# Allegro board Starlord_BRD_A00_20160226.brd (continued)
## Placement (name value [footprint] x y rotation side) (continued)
R2030  10KR2J-3-GP  [R402H16]  109.5 31.13 180 bottom
R2039  10KR2J-3-GP  [R402H16]  113.21 24.68 90 bottom
R2040  10KR2J-3-GP  [R402H16]  114.35 27.91 0 bottom
R2041  10KR2J-3-GP  [R402H16]  109.4 19.96 0 bottom
R2042  10KR2J-3-GP  [R402H16]  111.99 19.8 0 bottom
R2043  10KR2J-3-GP  [R402H16]  108.56 19.96 0 bottom
R2044  10KR2J-3-GP  [R402H16]  112.88 30.88 0 bottom
R2045  10KR2J-3-GP  [R402H16]  136.57 18.38 0 top
R2046  10KR2J-3-GP  [R402H16]  114.6 31.59 0 bottom
R2047  10KR2J-3-GP  [R402H16]  115.49 31.59 0 bottom
R2048  51KR2J-1-GP  [R402H16]  111.17 31.13 0 bottom
R2049  51KR2J-1-GP  [R402H16]  112.04 30.88 0 bottom
R2101  -  [0R0402-PAD]  55.17 9.49 180 bottom
R2102  0R2J-2-GP  [R402H16]  56.01 9.44 180 bottom
R2106  -  [0R0603-PAD]  72.03 5.07 0 top
R2107  -  [0R0603-PAD]  120.11 38.55 90 top
R2108  -  [0R0603-PAD]  114.7 42.36 90 top
R2109  -  [0R0603-PAD]  137.72 42.26 90 bottom
R2110  -  [0R0603-PAD]  137.72 43.53 90 bottom
R2111  -  [0R0603-PAD]  135.48 39.64 90 bottom
R2402  -  [0R0402-PAD]  179.02 30.75 90 top
R2403  -  [0R0402-PAD]  185.32 29.79 270 bottom
R2405  10R2F-L-GP  [R402H14]  198.55 42.38 270 bottom
R2407  -  [0R0402-PAD]  187.96 28.74 180 bottom
R2414  4K7R2J-2-GP  [R402H16]  134.75 5.76 270 top
R2415  10KR2J-3-GP  [R402H16]  186.21 27.7 0 bottom
R2417  100KR2J-1-GP  [R402H16]  190.55 41.39 270 bottom
R2418  0R2J-2-GP  [R402H16]  189.28 41.34 180 bottom
R2419  -  [0R0402-PAD]  198.65 41.47 90 bottom
R2421  330R2J-3-GP  [R402H16]  190.22 31.08 180 bottom
R2422  330R2J-3-GP  [R402H16]  185.07 31.08 180 bottom
R2423  330R2J-3-GP  [R402H16]  189.23 29.15 90 bottom
R2424  20KR2F-L-GP  [R402H16]  195.68 44.11 180 bottom
R2429  10KR2J-3-GP  [R402H16]  189.25 38.04 180 bottom
R2430  10KR2J-3-GP  [R402H16]  187.2 41.49 90 bottom
R2432  1KR2J-1-GP  [R402H16]  191.03 30.95 0 bottom
R2434  100KR2J-1-GP  [R402H16]  198.78 34.61 90 bottom
R2435  -  [0R0402-PAD]  185.08 34.43 0 bottom
R2436  100KR2J-1-GP  [R402H16]  184.96 32.76 180 bottom
R2437  43R2J-GP  [R402H16]  178.87 33.54 270 top
R2441  100KR2F-L1-GP  [R402H16]  187.78 31.11 0 bottom
R2442  64K9R2F-1-GP  [R402H16]  186.32 30.6 270 bottom
R2443  33KR2F-GP  [R402H16]  191.82 32.22 90 bottom
R2444  100KR2F-L1-GP  [R402H16]  190.57 32.81 0 bottom
R2445  -  [0R0402-PAD]  190.52 28.72 180 bottom
R2446  -  [0R0603-PAD]  201.67 33.65 270 top
R2447  0R2J-2-GP  [R402H16]  199.13 35.96 0 bottom
R2448  10KR2F-2-GP  [R402H16]  196.49 44.11 0 bottom
R2449  100KR2J-1-GP  [R402H16]  185.7 43.76 180 bottom
R2450  100KR2J-1-GP  [R402H16]  185.5 42.38 90 bottom
R2451  100KR2J-1-GP  [R402H16]  192.68 30.95 180 bottom
R2454  100KR2J-1-GP  [R402H16]  181.84 25.54 0 top
R2459  0R2J-2-GP  [R402H16]  198.3 35.96 0 bottom
R2462  -  [0R0402-PAD]  187.81 43.53 90 bottom
R2463  1KR2J-1-GP  [R402H16]  182.7 25.54 180 top
R2470  -  [0R0402-PAD]  198.35 39.84 270 bottom
R2471  0R2J-2-GP  [R402H16]  198.35 40.66 270 bottom
R2472  -  [0R0402-PAD]  193.67 36.72 90 bottom
R2473  10KR2J-3-GP  [R402H16]  191.79 28.31 270 bottom
R2474  0R2J-2-GP  [R402H16]  179.63 52.67 0 top
R2475  -  [0R0402-PAD]  178.74 52.67 0 top
R2480  100KR2J-1-GP  [R402H16]  134.72 6.62 270 top
R2489  100KR2J-1-GP  [R402H16]  186.31 32.73 270 bottom
R2494  0R2J-2-GP  [R402H16]  188.01 32.83 270 bottom
R2495  100KR2J-1-GP  [R402H16]  186.51 43.63 0 bottom
R2496  100KR2J-1-GP  [R402H16]  193.67 35.02 270 bottom
R2497  0R2J-2-GP  [R402H16]  185.34 28.97 270 bottom
R2501  4K7R2J-2-GP  [R402H16]  84.45 12.67 0 bottom
R2503  10R2F-L-GP  [R402H14]  74.09 7.33 90 bottom
R2504  10MR2J-L-GP  [R402H16]  71.88 7.43 90 bottom
R2510  10KR2F-2-GP  [R402H16]  184.88 43.76 0 bottom
R2515  -  [0R0402-PAD]  80.72 12.67 180 bottom
R2601  0R2J-2-GP  [R402H16]  139.98 22.29 270 bottom
R2602  -  [0R0402-PAD]  144.58 20.72 270 bottom
R2603  7K5R2F-1-GP  [R402H16]  133.83 24.2 180 bottom
R2604  7K5R2F-1-GP  [R402H16]  139.98 23.13 90 bottom
R2607  10KR2J-3-GP  [R402H16]  144.58 19.9 270 bottom
R2608  27KR2F-L-GP  [R402H16]  122.12 29.46 90 bottom
R2609  10R2F-L-GP  [R402H14]  122.12 28.64 90 bottom
R2610  NTC-100K-8-GP  [NTC-603H38]  122.86 31.72 180 bottom
R2611  -  [0R0402-PAD]  194.21 41.57 90 bottom
R2612  -  [0R0402-PAD]  149.02 77.94 90 top
R2613  -  [0R0402-PAD]  149.02 77.05 90 top
R2614  -  [0R0402-PAD]  149.02 76.17 90 top
R2615  0R2J-2-GP  [R402H16]  144.58 21.53 270 bottom
R2702  -  [0R0805-PAD]  28.4 16.32 180 bottom
R2703  -  [0R0603-PAD]  24.08 11.68 180 bottom
R2704  -  [0R0805-PAD]  30.1 16.32 180 bottom
R2705  0R2J-2-GP  [R402H16]  24.79 23.46 270 top
R2706  -  [0R0805-PAD]  20.32 10.46 180 bottom
R2708  -  [0R0402-PAD]  29.26 13.81 270 top
R2709  200KR2F-L-GP  [R402H16]  27.99 11.01 90 top
R2710  0R2J-2-GP  [R402H16]  24.79 22.65 270 top
R2711  100KR2J-1-GP  [R402H16]  19 12.08 0 bottom
R2713  -  [0R0402-PAD]  24.79 21.84 270 top
R2714  -  [0R0402-PAD]  29.28 14.62 270 top
R2716  -  [0R0402-PAD]  29.28 16.4 270 top
R2717  2K2R2J-2-GP  [R402H16]  25.88 13.07 0 bottom
R2718  -  [0R0402-PAD]  32.76 19.24 270 top
R2719  -  [0R0402-PAD]  29.28 19.96 270 top
R2720  -  [0R0402-PAD]  29.28 18.18 270 top
R2722  100KR2J-1-GP  [R402H16]  27.99 11.9 270 top
R2723  -  [0R0402-PAD]  20.01 15.41 0 bottom
R2724  -  [0R0402-PAD]  24.48 19.96 0 bottom
R2725  -  [0R0402-PAD]  26.72 11.47 180 top
R2726  10KR2J-3-GP  [R402H16]  19.3 28.85 0 bottom
R2727  20KR2J-L2-GP  [R402H16]  18.46 28.85 180 bottom
R2728  100KR2J-1-GP  [R402H16]  30.28 12.41 0 top
R2731  -  [0R0805-PAD]  29.97 22.37 0 top
R2732  0R2J-2-GP  [R402H16]  29.28 17.29 90 top
R2905  -  [0R0402-PAD]  18.03 24.53 270 bottom
R2906  -  [0R0603-PAD]  16.31 14.7 180 top
R2907  -  [0R0603-PAD]  17.02 19.93 90 top
R2908  10R2F-L-GP  [R402H14]  16.97 17.21 90 bottom
R2909  -  [0R0603-PAD]  20.24 22.75 90 top
R2910  10R2F-L-GP  [R402H14]  16.97 21.56 90 bottom
R2911  -  [0R0603-PAD]  17.58 14.7 180 top
R2912  2K2R2J-2-GP  [R402H16]  16.97 18.1 270 bottom
R2913  2K2R2J-2-GP  [R402H16]  16.97 23.44 90 bottom
R2919  10KR2J-3-GP  [R402H16]  16.97 18.99 270 bottom
R2920  10KR2J-3-GP  [R402H16]  16.97 19.85 270 bottom
R2921  -  [0R0402-PAD]  16.97 22.62 90 bottom
R2922  -  [0R0402-PAD]  16.97 16.32 270 bottom
R2923  -  [0R0603-PAD]  17.04 21.23 90 top
R3401  -  [0R0402-PAD]  20.01 45 0 bottom
R3402  -  [0R0402-PAD]  18.39 45.51 0 bottom
R3403  20KR2F-L-GP  [R402H16]  24.1 43.91 270 bottom
R3404  22K1R2F-L-GP  [R402H16]  24.1 44.72 270 bottom
R3405  -  [0R0402-PAD]  20.83 45 0 bottom
R3406  -  [0R0402-PAD]  19.2 45.51 0 bottom
R3501  100KR2J-1-GP  [R402H16]  20.75 39.44 270 bottom
R3605  -  [0R0402-PAD]  22.02 54.04 270 top
R3606  -  [0R0402-PAD]  22.02 54.86 270 top
R3609  -  [0R0402-PAD]  22.02 51.88 270 top
R3610  -  [0R0402-PAD]  22.02 52.7 270 top
R3611  -  [0R0402-PAD]  22.15 31.69 270 top
R3612  -  [0R0402-PAD]  22.15 29.53 270 top
R3613  -  [0R0402-PAD]  22.15 30.34 270 top
R3614  -  [0R0402-PAD]  22.15 32.5 270 top
R3701  -  [0R0402-PAD]  26.87 41.11 0 top
R3702  -  [0R0402-PAD]  28.17 41.55 90 top
R3703  100KR2J-1-GP  [R402H16]  36.75 37.18 180 top
R3704  10KR2F-2-GP  [R402H16]  35.86 37.18 180 top
R3705  -  [0R0402-PAD]  30.28 37.18 0 top
R3706  -  [0R0402-PAD]  38.4 41.37 270 top
R3707  2K2R2J-2-GP  [R402H16]  31.16 37.18 180 top
R3708  4K7R2J-2-GP  [R402H16]  32.05 37.18 180 top
R3709  -  [0R0402-PAD]  31.37 48.35 0 top
R3710  -  [0R0402-PAD]  24.23 43.76 270 top
R3711  200KR2J-L2-GP  [R402H16]  38.4 40.38 90 top
R3712  200KR2J-L2-GP  [R402H16]  38.4 42.26 90 top
R3713  909KR2F-GP  [R402H16]  29.03 49.01 270 top
R3714  909KR2F-GP  [R402H16]  30.38 49.57 180 top
R3715  909KR2F-GP  [R402H16]  20.75 95.95 270 top
R3716  301KR2F-1-GP  [R402H16]  20.65 96.79 270 top
R3717  10KR2F-2-GP  [R402H16]  40.69 41.37 270 top
R3718  -  [0R0402-PAD]  38.4 44.03 270 top
R3719  0R2J-2-GP  [R402H16]  38.4 43.15 270 top
R3720  0R2J-2-GP  [R402H16]  32.18 46.57 180 top
R3721  0R2J-2-GP  [R402H16]  33.07 46.57 180 top
R3722  10KR2F-2-GP  [R402H16]  27.1 46.83 90 top
R3723  10KR2F-2-GP  [R402H16]  23.65 48.66 180 top
R3801  100KR2J-1-GP  [R402H16]  33.04 63.97 90 top
R3802  100KR2J-1-GP  [R402H16]  34.82 63.97 270 top
R3803  4K99R2F-L-GP  [R402H16]  27.76 53.43 0 top
R3810  4K7R2J-2-GP  [R402H16]  29.01 61.31 270 top
R3811  4K7R2J-2-GP  [R402H16]  38.4 60.42 90 top
R3812  10KR2J-3-GP  [R402H16]  37.39 64.13 180 top
R3813  10KR2J-3-GP  [R402H16]  39.75 64.35 270 top
R3814  10KR2J-3-GP  [R402H16]  38.91 62.86 270 top
R3815  4K7R2J-2-GP  [R402H16]  38.5 58.18 270 top
R3816  4K7R2J-2-GP  [R402H16]  38.5 59 270 top
R3817  4K7R2J-2-GP  [R402H16]  29.01 56.23 90 top
R3818  4K7R2J-2-GP  [R402H16]  29.01 57.09 90 top
R3819  4K7R2J-2-GP  [R402H16]  29.01 58.79 90 top
R3820  4K7R2J-2-GP  [R402H16]  29.01 57.95 90 top
R3821  4K7R2J-2-GP  [R402H16]  38.2 56.18 270 top
R3822  4K7R2J-2-GP  [R402H16]  38.2 55.34 270 top
R3823  4K7R2J-2-GP  [R402H16]  28.6 53.43 180 top
R3824  4K7R2J-2-GP  [R402H16]  29.44 53.43 180 top
R3830  2MR2F-GP  [R402H16]  15.44 96.41 180 top
R3831  2MR2F-GP  [R402H16]  15.44 94.73 0 top
R3832  -  [0R0402-PAD]  18.67 91.79 270 top
R3833  -  [0R0402-PAD]  18.67 92.6 270 top
R3834  -  [0R0402-PAD]  21.77 92.8 270 top
R3835  -  [0R0402-PAD]  21.77 93.62 270 top
R3836  -  [0R0402-PAD]  17.47 97.53 270 top
R3837  -  [0R0402-PAD]  17.47 96.71 270 top
R3838  -  [0R0402-PAD]  16.56 99.69 270 top
R3839  -  [0R0402-PAD]  16.56 98.87 270 top
R3842  0R2J-2-GP  [R402H16]  29.01 60.47 270 top
R3843  -  [0R0402-PAD]  36.57 64.13 180 top
R3844  0R2J-2-GP  [R402H16]  41.07 63.52 90 top
R3845  0R2J-2-GP  [R402H16]  41.07 62.7 90 top
R3846  -  [0R0402-PAD]  29.01 59.63 270 top
R3847  0R2J-2-GP  [R402H16]  24.48 61.03 90 top
R3848  0R2J-2-GP  [R402H16]  24.48 61.87 90 top
R3849  -  [0R0402-PAD]  26.21 61.87 90 top
R3850  -  [0R0402-PAD]  26.21 61.03 90 top
R4002  -  [0R0402-PAD]  162.02 100.35 270 bottom
R4005  1KR2J-1-GP  [R402H16]  162.02 101.16 90 bottom
R4006  20KR2F-L-GP  [R402H16]  117.47 18 0 bottom
R4009  10KR2J-3-GP  [R402H16]  116.66 18 0 bottom
R4010  -  [0R0402-PAD]  130.35 101.95 270 bottom
R4011  -  [0R0402-PAD]  161.34 102.86 180 bottom
R4017  -  [0R0402-PAD]  86.82 90.19 0 top
R4018  0R2J-2-GP  [R402H16]  95.86 92.85 90 top
R4019  0R2J-2-GP  [R402H16]  100 92.55 270 bottom
R4021  -  [0R1206-PAD]  106.12 95.19 90 top
R4022  -  [0R1206-PAD]  106.12 93.08 270 top
R4023  -  [0R0402-PAD]  104.54 11.35 180 bottom
R4024  -  [0R0402-PAD]  106.2 16.55 0 bottom
R4026  10KR2J-3-GP  [R402H16]  99.06 10.71 180 bottom
R4027  10KR2J-3-GP  [R402H16]  109.02 96.87 90 bottom
R4028  10KR2J-3-GP  [R402H16]  109.02 95.98 90 bottom
R4029  -  [0R0402-PAD]  158.72 104.69 180 bottom
R4030  -  [0R0402-PAD]  159.61 104.69 180 bottom
R4031  100KR2J-1-GP  [R402H16]  161.39 104.69 180 bottom
R4032  100KR2J-1-GP  [R402H16]  157.83 104.69 180 bottom
R4033  0R2J-2-GP  [R402H16]  160.5 104.69 180 bottom
R4036  -  [0R0402-PAD]  111.25 15.59 270 bottom
R4038  -  [0R0402-PAD]  111.25 14.7 270 bottom
R4042  -  [0R0402-PAD]  95.88 90.67 90 top
R4043  20KR2J-L2-GP  [R402H16]  73.58 13.33 90 top
R4044  -  [0R0402-PAD]  97.57 90.67 90 top
R4045  -  [0R1206-PAD]  93.57 86.15 0 top
R4046  10KR2J-3-GP  [R402H16]  73.58 14.22 270 top
R4101  0R5J-5-GP  [R805H24]  113.56 12.97 270 bottom
R4102  0R2J-2-GP  [R402H16]  108.46 13.76 90 bottom
R4103  0R3J-0-U-GP  [R603H22]  113.38 10.58 270 bottom
R4301  -  [0R0402-PAD]  166.95 24.27 90 top
R4302  0R2J-2-GP  [R402H16]  177.85 93.82 90 top
R4303  0R2J-2-GP  [R402H16]  173.4 94.33 270 top
R5411  4K7R2J-2-GP  [R402H16]  21.05 70.32 180 bottom
R5412  4K7R2J-2-GP  [R402H16]  21.77 68.04 0 bottom
R5413  4K7R2J-2-GP  [R402H16]  22.78 60.16 270 top
R5414  4K7R2J-2-GP  [R402H16]  22.78 61 270 top
R5415  4K7R2J-2-GP  [R402H16]  21.94 70.32 180 bottom
R5416  4K7R2J-2-GP  [R402H16]  22.66 68.04 0 bottom
R5417  4K7R2J-2-GP  [R402H16]  22.83 70.32 180 bottom
R5418  4K7R2J-2-GP  [R402H16]  23.54 68.04 0 bottom
R5419  4K7R2J-2-GP  [R402H16]  23.72 70.32 180 bottom
R5420  4K7R2J-2-GP  [R402H16]  20.12 65.88 0 bottom
R5501  -  [0R0402-PAD]  64.31 90.14 0 top
R5502  0R2J-2-GP  [R402H16]  104.09 101.03 90 top
R5503  -  [0R0402-PAD]  100.53 96.74 180 top
R5506  100R2J-2-GP  [R402H14]  93.19 95.52 90 top
R5507  0R3J-0-U-GP  [R603H22]  70.61 100.83 270 top
R5510  -  [0R0603-PAD]  73.2 92.98 90 top
R5511  -  [0R0603-PAD]  73.2 91.56 90 top
R5513  0R3J-0-U-GP  [R603H22]  58.19 97.96 90 top
R5514  0R6J-L-GP  [R1206H26]  78.18 96.64 180 top
R5516  0R3J-0-U-GP  [R603H22]  56.67 93.79 270 top
R5520  0R3J-0-U-GP  [R603H22]  54.3 93.01 270 top
R5540  -  [0R0402-PAD]  66.06 93.06 90 top
R5701  -  [0R0603-PAD]  26.39 71.47 270 top
R5702  180R2J-1-GP  [R402H16]  18.34 66.13 0 top
R5703  180R2J-1-GP  [R402H16]  18.34 63.21 0 top
R5704  180R2J-1-GP  [R402H16]  17.07 64.61 0 top
R5705  180R2J-1-GP  [R402H16]  16.94 67.36 0 top
R5706  2K2R2J-2-GP  [R402H16]  22.27 63.67 90 bottom
R5707  2K2R2J-2-GP  [R402H16]  20.47 60.6 180 top
R5710  4K3R2J-GP  [R402H16]  20.95 68.04 180 bottom
R5715  -  [0R0603-PAD]  24.43 58.39 180 top
R5716  0R3J-0-U-GP  [R603H22]  25.7 58.39 180 top
R5721  10KR2J-3-GP  [R402H16]  21.03 58.03 90 bottom
R5722  -  [0R0402-PAD]  20.12 64.2 0 bottom
R5723  -  [0R0402-PAD]  19.25 58.03 270 bottom
R6001  -  [0R0402-PAD]  178.26 26.1 270 top
R6002  -  [0R0402-PAD]  178.18 17.8 180 top
R6003  -  [0R0603-PAD]  176.81 20.97 90 top
R6005  0R2J-2-GP  [R402H16]  172.26 16.96 180 top
R6006  -  [0R0603-PAD]  171.42 20.01 180 top
R6007  0R2J-2-GP  [R402H16]  171.37 16.96 180 top
R6120  10KR2J-3-GP  [R402H16]  166.42 28.67 90 bottom
R6301  -  [0R0402-PAD]  200.15 17.75 180 top
R6302  -  [0R0603-PAD]  199.95 19.98 180 top
R6303  10KR2J-3-GP  [R402H16]  200.2 15.21 180 top
R6304  10KR2J-3-GP  [R402H16]  200.58 16.48 90 top
R6305  -  [0R0402-PAD]  195.25 14.06 90 top
R6307  -  [0R0603-PAD]  202.06 10.71 180 top
R6401  499R2F-2-GP  [R402H16]  120.19 10.25 90 bottom
R6402  330R2J-3-GP  [R402H16]  113.92 18.74 180 bottom
R6403  -  [0R0402-PAD]  114.98 10.71 180 bottom
R6404  -  [0R0402-PAD]  115.29 19.02 90 bottom
R6501  0R3J-0-U-GP  [R603H22]  140.97 18.25 270 top
R6502  0R3J-0-U-GP  [R603H22]  125.12 21.53 180 bottom
R6503  100R3J-4-GP  [R603H22]  124.69 18.76 180 bottom
R6504  20KR2F-L-GP  [R402H16]  117.57 20.46 270 bottom
R6505  0R2J-2-GP  [R402H16]  133.5 21.15 90 top
R6506  0R2J-2-GP  [R402H16]  133.5 22.01 90 top
R6507  51KR2J-1-GP  [R402H16]  130.99 21.4 90 top
R6508  100KR2J-1-GP  [R402H16]  129.72 20.79 0 top
R6509  100KR2J-1-GP  [R402H16]  139.39 20.92 0 bottom
R6510  -  [0R0402-PAD]  141.1 17.11 270 top
R6511  10KR2J-3-GP  [R402H16]  130.68 18.25 0 top
R6512  -  [0R0402-PAD]  145.01 22.9 180 bottom
R6513  1KR2J-1-GP  [R402H16]  149.15 20.92 0 top
R6514  0R3J-0-U-GP  [R603H22]  123.72 21.53 180 bottom
R6605  -  [0R0603-PAD]  172.64 53.18 90 top
R6606  -  [0R0603-PAD]  172.64 52.04 90 top
R6801  0R2J-2-GP  [R402H16]  146.25 6.16 0 top
R6802  0R2J-2-GP  [R402H16]  145.34 6.16 180 top
R6901  0R3J-0-U-GP  [R603H22]  44.98 34.99 180 top
R6902  100KR2J-1-GP  [R402H16]  32.94 27.4 270 top
R6904  1K5R2F-2-GP  [R402H16]  45.26 31.33 90 top
R6905  0R2J-2-GP  [R402H16]  45.26 29.56 270 top
R6906  0R2J-2-GP  [R402H16]  45.26 30.45 270 top
R6907  20KR2J-L2-GP  [R402H16]  37.77 35.02 180 top
R6908  10KR2J-3-GP  [R402H16]  39.55 22.83 180 top
R6909  10KR2J-3-GP  [R402H16]  40.44 22.83 0 top
R6910  10KR2J-3-GP  [R402H16]  38.66 22.83 180 top
R6911  10KR2J-3-GP  [R402H16]  37.77 22.83 0 top
R6912  10KR2J-3-GP  [R402H16]  35.99 22.83 180 top
R6913  10KR2J-3-GP  [R402H16]  36.88 22.83 0 top
R6914  10KR2J-3-GP  [R402H16]  35.1 22.83 180 top
R6915  10KR2J-3-GP  [R402H16]  34.21 22.83 0 top
R6916  10KR2J-3-GP  [R402H16]  32.94 24.22 90 top
R6917  10KR2J-3-GP  [R402H16]  32.94 23.33 270 top
R6918  10KR2J-3-GP  [R402H16]  32.94 25.11 90 top
R6919  10KR2J-3-GP  [R402H16]  32.94 26 270 top
R6920  0R2J-2-GP  [R402H16]  33.55 33.16 0 top
R6921  0R2J-2-GP  [R402H16]  42.21 22.83 0 top
R6922  0R2J-2-GP  [R402H16]  43.1 22.83 0 top
R6923  0R2J-2-GP  [R402H16]  43.99 22.83 0 top
R6924  0R2J-2-GP  [R402H16]  40.44 35.02 180 top
R6925  0R2J-2-GP  [R402H16]  41.32 22.83 0 top
R6926  0R2J-2-GP  [R402H16]  41.32 35.02 180 top
R6928  0R2J-2-GP  [R402H16]  39.55 35.02 180 top
R6929  0R2J-2-GP  [R402H16]  38.66 35.02 180 top
R7001  100KR2J-1-GP  [R402H16]  16.25 83.4 180 top
R7002  0R2J-2-GP  [R402H16]  122.25 1.72 90 bottom
R7003  -  [0R0402-PAD]  121.66 3.01 180 bottom
R7004  -  [0R0402-PAD]  176.43 40.66 270 top
R7005  10KR2J-3-GP  [R402H16]  177.34 46.32 0 top
R7006  10KR2J-3-GP  [R402H16]  179.47 45.61 270 top
R7007  -  [0R0402-PAD]  177.8 45.08 90 top
R7008  -  [0R0402-PAD]  125.5 6.24 180 bottom
R7009  -  [0R0402-PAD]  122.96 6.37 180 bottom
R7010  -  [0R0402-PAD]  123.82 6.24 180 bottom
R7011  100KR2J-1-GP  [R402H16]  15.42 83.98 180 top
R7012  -  [0R0402-PAD]  122.07 6.37 180 bottom
R7013  -  [0R0402-PAD]  124.66 6.24 180 bottom
R7018  100KR2J-1-GP  [R402H16]  123.42 11.17 90 bottom
RN801  SRN2K2J-1-GP  [ARES2H16]  122.05 24.93 180 bottom
RN803  SRN2K2J-1-GP  [ARES2H16]  120.04 24.93 180 bottom
RN1201  SRN1KJ-7-GP  [SMD-ARES4H18]  72.66 45.19 0 top
RN1301  SRN1KJ-7-GP  [SMD-ARES4H18]  50.78 40.32 0 top
RN1601  SRN10KJ-6-GP  [ARES8-CN24-MUH20]  130.3 38.17 90 bottom
RN1602  SRN0J-6-GP  [SMD-ARES4H20]  113.59 21.56 180 top
RN1702  SRN0J-6-GP  [SMD-ARES4H20]  111.68 22.7 180 bottom
RN1703  SRN10KJ-5-GP  [ARES2H18]  100.46 18 90 bottom
RN1704  SRN10KJ-6-GP  [ARES8-CN24-MUH20]  105.92 19.57 180 bottom
RN1801  SRN20KJ-1-GP  [SMD-ARES4H20]  69.85 4.94 90 top
RN1802  SRN1KJ-7-GP  [SMD-ARES4H18]  94.28 30.6 180 top
RN1803  SRN10J-1-GP  [ARES8-CN24-UH18]  91.67 30.67 0 top
RN1806  SRN0J-7-GP-U  [ARES8-CN24H22]  89.18 42.61 180 top
RN1807  SRN2K2J-4-GP  [ARES8-CN24-UH20]  112.52 27.42 180 bottom
RN1810  SRN10KJ-5-GP  [ARES2H18]  104.21 16.76 270 top
RN1811  SRN2K2J-1-GP  [ARES2H16]  101.17 15.38 90 top
RN1812  SRN10KJ-6-GP  [ARES8-CN24-MUH20]  93.85 40.83 0 top
RN1813  SRN10KJ-6-GP  [ARES8-CN24-MUH20]  94.28 38.42 270 top
RN1814  SRN2K2J-1-GP  [ARES2H16]  28.75 37.18 0 top
RN1815  SRN2K2J-1-GP  [ARES2H16]  38.78 38.95 90 top
RN1902  SRN33J-5-GP-U  [SMD-ARES4H18]  91.97 48.25 270 top
RN2007  SRN1KJ-7-GP  [SMD-ARES4H18]  118.03 27.04 0 bottom
RN2008  SRN2K2J-1-GP  [ARES2H16]  116.03 27.55 0 bottom
RN2009  SRN10KJ-5-GP  [ARES2H18]  117.3 37.81 90 top
RN2402  SRN4K7J-8-GP  [SMD-ARES4H18]  173 31.82 180 top
RN2403  SRN10KJ-6-GP  [ARES8-CN24-MUH20]  180.49 28.01 270 top
RN2404  SRN10KJ-6-GP  [ARES8-CN24-MUH20]  178.43 28.01 90 top
RN2405  SRN100KJ-5-GP  [ARES8-CN24H20]  173.12 43.12 90 top
RN2406  SRN10J-8-GP  [SMD-ARES4-2H18-U]  198.88 43.98 90 bottom
RN2407  SRN10KJ-5-GP  [ARES2H18]  170.99 43.4 180 top
RN2409  SRN100KJ-5-GP  [ARES8-CN24H20]  193.88 44.11 180 bottom
RN2410  SRN100KJ-5-GP  [ARES8-CN24H20]  172.69 40.25 270 top
RN2411  SRN100KJ-5-GP  [ARES8-CN24H20]  180.86 35.3 270 top
RN2412  SRN100KJ-5-GP  [ARES8-CN24H20]  190.9 43.86 0 bottom
RN2502  SRN10J-8-GP  [SMD-ARES4-2H18-U]  73.91 4.97 270 bottom
RN2503  SRN10J-8-GP  [SMD-ARES4-2H18-U]  82.17 12.84 0 bottom
RN2602  SRN2K2J-1-GP  [ARES2H16]  135.1 33.32 90 bottom
RN2603  SRN2K2J-1-GP  [ARES2H16]  171.85 34.56 270 top
RN2604  SRN2K2J-1-GP  [ARES2H16]  175.84 29.53 90 top
RN2701  SRN1KJ-7-GP  [SMD-ARES4H18]  31.39 12.28 180 bottom
RN2901  SRN2K2J-1-GP  [ARES2H16]  16.94 18.25 90 top
RN4302  SRN100J-4-GP  [ARES8-CN24H20]  163.7 25.92 180 top
RN5501  SRN100J-4-GP  [ARES8-CN24H20]  97.33 96.99 0 top
RN5502  SRN100KJ-5-GP  [ARES8-CN24H20]  99.87 99.15 90 top
RN5503  SRN33J-5-GP-U  [SMD-ARES4H18]  61.29 90.24 90 top
RN6501  SRN10KJ-5-GP  [ARES2H18]  128.83 21.96 90 bottom
RN6502  SRN33J-5-GP-U  [SMD-ARES4H18]  129.21 18.13 180 top
RN6503  SRN2K2J-1-GP  [ARES2H16]  132.64 18 270 top
RN6801  SRN0J-7-GP-U  [ARES8-CN24H22]  149.15 5.93 180 top
RN6901  SRN2K2J-1-GP  [ARES2H16]  43.99 37.3 90 top
RN7001  SRN0J-6-GP  [SMD-ARES4H20]  116.84 22.04 90 bottom
SKT251  SKT-G6179HT0321-001-GP  [G6179HT0321-001]  80.82 6.67 90 bottom
SPI25  N25Q128A13ESEC0F-GP  [SOIC8-1H86]  80.87 6.69 270 bottom
SPK1  HR-CON6-1-GP-U  [A1001WR-S06PN6BT1TS2R-U]  12.7 5.14 180 bottom
SPR1  SPRING-171-GP  [SPR5128H111]  116.7 92.71 0 top
SPR2  SPRING-171-GP  [SPR5128H111]  89.7 53.71 0 top
SPR3  SPRING-171-GP  [SPR5128H111]  41.7 19.71 0 top
SPR4  SPRING-15-GP  [SPR6238H60]  117.7 91.71 0 bottom
SSD1  SKT-MINI67P-15-GP  [AS0BC2Y-S30BM-7H]  200.1 22.19 270 bottom
TC3501  SC100U6D3V6MX-GP  [C1206H71]  17.17 42.49 0 bottom
TCBD1  JAE-CON32-2-GP-U  [FL10F032HA2R3000]  62.9 96.91 0 bottom
THM261  NCT7718W-GP  [MSOP8-1H44]  137.56 25.62 270 bottom
TP401  TPAD14-OP-GP  [TPAD14-OP]  124.48 73.09 270 top
TP402  TPAD14-OP-GP  [TPAD14-OP]  129.69 77.69 270 bottom
TP403  TPAD14-OP-GP  [TPAD14-OP]  127.02 38.55 90 top
TP404  TPAD14-OP-GP  [TPAD14-OP]  104.57 37.66 180 top
TP405  TPAD14-OP-GP  [TPAD14-OP]  127.48 68.5 270 top
TP406  TPAD14-OP-GP  [TPAD14-OP]  126.46 67.73 270 top
TP407  TPAD14-OP-GP  [TPAD14-OP]  125.5 66.87 270 top
TP408  TPAD14-OP-GP  [TPAD14-OP]  129.39 68.95 270 bottom
TP601  TPAD14-OP-GP  [TPAD14-OP]  103.45 76.52 90 top
TP602  TPAD14-OP-GP  [TPAD14-OP]  99.74 76.14 90 top
TP603  TPAD14-OP-GP  [TPAD14-OP]  99.95 77.36 90 top
TP604  TPAD14-OP-GP  [TPAD14-OP]  98.7 77.39 90 top
TP605  TPAD14-OP-GP  [TPAD14-OP]  110.56 43.7 90 top
TP606  TPAD14-OP-GP  [TPAD14-OP]  110.84 42.13 90 top
TP607  TPAD14-OP-GP  [TPAD14-OP]  106.22 39.21 90 top
TP608  TPAD14-OP-GP  [TPAD14-OP]  107.7 39.97 90 top
TP609  TPAD14-OP-GP  [TPAD14-OP]  103.3 38.4 90 top
TP610  TPAD14-OP-GP  [TPAD14-OP]  102.44 37.23 90 top
TP611  TPAD14-OP-GP  [TPAD14-OP]  101.14 37.89 90 top
TP612  TPAD14-OP-GP  [TPAD14-OP]  123.24 73.09 90 top
TP613  TPAD14-OP-GP  [TPAD14-OP]  121.92 73.07 90 top
TP614  TPAD14-OP-GP  [TPAD14-OP]  103.02 75.35 90 top
TP615  TPAD14-OP-GP  [TPAD14-OP]  100.99 76.67 90 top
TP617  TPAD14-OP-GP  [TPAD14-OP]  109.83 68.6 90 top
TP618  TPAD14-OP-GP  [TPAD14-OP]  126.03 75.71 90 top
TP619  TPAD14-OP-GP  [TPAD14-OP]  125.93 76.93 90 top
TP620  TPAD14-OP-GP  [TPAD14-OP]  127.25 76.01 90 top
TP621  TPAD14-OP-GP  [TPAD14-OP]  126.11 74.46 90 top
TP622  TPAD14-OP-GP  [TPAD14-OP]  123.34 77.82 90 top
TP623  TPAD14-OP-GP  [TPAD14-OP]  124.86 77.56 90 top
TP624  TPAD14-OP-GP  [TPAD14-OP]  123.77 76.67 90 top
TP625  TPAD14-OP-GP  [TPAD14-OP]  124.76 74.59 180 top
TP626  TPAD14-OP-GP  [TPAD14-OP]  123.34 80.31 0 top
TP627  TPAD14-OP-GP  [TPAD14-OP]  121.05 80.94 0 top
TP628  TPAD14-OP-GP  [TPAD14-OP]  123.32 79.06 0 top
TP629  TPAD14-OP-GP  [TPAD14-OP]  123.32 81.68 0 top
TP630  TPAD14-OP-GP  [TPAD14-OP]  122.25 79.72 0 top
TP631  TPAD14-OP-GP  [TPAD14-OP]  122.3 80.97 0 top
TP632  TPAD14-OP-GP  [TPAD14-OP]  121 79.7 0 top
TP633  TPAD14-OP-GP  [TPAD14-OP]  121.61 82.06 0 top
TP634  TPAD14-OP-GP  [TPAD14-OP]  123.87 72.03 0 top
TP635  TPAD14-OP-GP  [TPAD14-OP]  122.63 72.03 0 top
TP636  TPAD14-OP-GP  [TPAD14-OP]  123.77 75.33 0 top
TP637  TPAD14-OP-GP  [TPAD14-OP]  122.55 75.43 0 top
TP638  TPAD14-OP-GP  [TPAD14-OP]  124.64 40.73 0 top
TP701  TPAD14-OP-GP  [TPAD14-OP]  122.78 54.17 0 top
TP707  TPAD14-OP-GP  [TPAD14-OP]  111.99 54.8 0 top
TP801  TPAD14-OP-GP  [TPAD14-OP]  125.47 65.65 0 top
TP1602  TPAD14-OP-GP  [TPAD14-OP]  122.6 33.11 0 top
TP1603  TPAD14-OP-GP  [TPAD14-OP]  124.13 34.94 0 top
TP1604  TPAD14-OP-GP  [TPAD14-OP]  124.64 36.06 0 top
TP1605  TPAD14-OP-GP  [TPAD14-OP]  129.54 67.68 180 bottom
TP1606  TPAD14-OP-GP  [TPAD14-OP]  123.37 70.91 0 top
TP1703  TPAD14-OP-GP  [TPAD14-OP]  101.09 44.97 270 top
TP1704  TPAD14-OP-GP  [TPAD14-OP]  102.49 44.57 270 top
TP1705  TPAD14-OP-GP  [TPAD14-OP]  133.35 78.81 270 bottom
TP1706  TPAD14-OP-GP  [TPAD14-OP]  108.35 45.46 270 top
TP1707  TPAD14-OP-GP  [TPAD14-OP]  106.02 43.27 270 top
TP1708  TPAD14-OP-GP  [TPAD14-OP]  109.73 42.78 270 top
TP1709  TPAD14-OP-GP  [TPAD14-OP]  125.88 37.1 0 top
TP1710  TPAD14-OP-GP  [TPAD14-OP]  99.34 45.71 0 top
TP1711  TPAD14-OP-GP  [TPAD14-OP]  110.64 21.38 0 top
TP1712  TPAD14-OP-GP  [TPAD14-OP]  111.61 22.17 0 top
TP1801  TPAD14-OP-GP  [TPAD14-OP]  119.78 33.65 0 top
TP1802  TPAD14-OP-GP  [TPAD14-OP]  123.34 61 0 top
TP1803  TPAD14-OP-GP  [TPAD14-OP]  123.9 62.12 0 top
TP1804  TPAD14-OP-GP  [TPAD14-OP]  116.18 33.04 0 top
TP1805  TPAD14-OP-GP  [TPAD14-OP]  117.55 33.19 0 top
TP1806  TPAD14-OP-GP  [TPAD14-OP]  119.51 32.45 0 top
TP1807  TPAD14-OP-GP  [TPAD14-OP]  94.99 48.3 0 top
TP1902  TPAD14-OP-GP  [TPAD14-OP]  101.06 40.25 0 top
TP1903  TPAD14-OP-GP  [TPAD14-OP]  91.74 45.38 0 top
TP2006  TPAD14-OP-GP  [TPAD14-OP]  118.57 33.9 270 top
TP2012  TPAD14-OP-GP  [TPAD14-OP]  115.16 34.31 270 top
TP2013  TPAD14-OP-GP  [TPAD14-OP]  116.41 34.26 270 top
TP2014  TPAD14-OP-GP  [TPAD14-OP]  116.89 39.69 270 top
TP2016  TPAD14-OP-GP  [TPAD14-OP]  113.31 34.61 270 top
TP2017  TPAD14-OP-GP  [TPAD14-OP]  114.81 32.94 270 top
TP2018  TPAD14-OP-GP  [TPAD14-OP]  109.52 39.11 270 top
TP2101  TPAD14-OP-GP  [TPAD14-OP]  108.98 41.8 0 top
TP2102  TPAD14-OP-GP  [TPAD14-OP]  107.7 42.71 0 top
TP2301  TPAD14-OP-GP  [TPAD14-OP]  102.23 76.67 0 top
TP2302  TPAD14-OP-GP  [TPAD14-OP]  101.55 75.51 0 top
TP2303  TPAD14-OP-GP  [TPAD14-OP]  104.7 76.75 0 top
TP2304  TPAD14-OP-GP  [TPAD14-OP]  105.92 76.67 0 top
TP2305  TPAD14-OP-GP  [TPAD14-OP]  99.74 36.06 0 top
TP2306  TPAD14-OP-GP  [TPAD14-OP]  100.1 37.25 0 top
TP2307  TPAD14-OP-GP  [TPAD14-OP]  106.25 35.7 0 top
TP2308  TPAD14-OP-GP  [TPAD14-OP]  125.86 35.88 0 top
TP2309  TPAD14-OP-GP  [TPAD14-OP]  127.28 36.85 0 top
TP2310  TPAD14-OP-GP  [TPAD14-OP]  124.89 78.83 0 top
TP2311  TPAD14-OP-GP  [TPAD14-OP]  126.01 78.17 0 top
TP2312  TPAD14-OP-GP  [TPAD14-OP]  124.81 76.04 0 top
TP2313  TPAD14-OP-GP  [TPAD14-OP]  122.25 78.45 0 top
TP2702  TPAD14-OP-GP  [TPAD14-OP]  29.13 12.79 180 top
TP2901  TPAD14-OP-GP  [TPAD14-OP]  27.3 59.68 180 top
TP2902  TPAD14-OP-GP  [TPAD14-OP]  38.33 65.27 180 top
TP3701  TPAD14-OP-GP  [TPAD14-OP]  29.82 40.56 0 top
TP3702  TPAD14-OP-GP  [TPAD14-OP]  29.69 39.34 0 top
TP3703  TPAD14-OP-GP  [TPAD14-OP]  33.96 37.94 0 top
TP6901  TPAD14-OP-GP  [TPAD14-OP]  43.61 35.53 0 top
TP6902  TPAD14-OP-GP  [TPAD14-OP]  43.61 34.26 0 top
TP6903  TPAD14-OP-GP  [TPAD14-OP]  45.52 32.35 0 top
TP6904  TPAD14-OP-GP  [TPAD14-OP]  42.54 34.92 0 top
TR3602  DLP11SN900HL2L-GP  [L125100-4P-4H37]  23.8 52.77 90 bottom
TR3603  DLP11SN900HL2L-GP  [L125100-4P-4H37]  23.82 32.45 270 bottom
TR3805  FILTER-4P-156-GP-U  [L125100-4PH24]  18.39 94.96 90 top
TR5501  DLP11SN900HL2L-GP  [L125100-4P-4H37]  66.98 91.53 180 top
TR6601  COIL-90OHM-100MHZ-5-GP  [L125100-4P-4H24]  172.29 49.98 0 top
TR6602  COIL-90OHM-100MHZ-5-GP  [L125100-4P-4H24]  172.29 47.35 0 top
U1701  74LVC1G07GW-GP  [SC70-5H44]  61.26 5.17 270 bottom
U1703  74LVC1G07GW-GP  [SC70-5H44]  57.33 3.39 270 bottom
U3401  TPS2544RTER-GP  [QFN16-G1D8-UH32]  22.35 48.35 0 bottom
U3501  SY6288DAAC-GP  [SOT-23-5H56]  22.6 41.65 90 bottom
U3502  SY6288DAAC-GP  [SOT-23-5H56]  22.6 37.18 90 bottom
U3701  CYPD2122-24LQXIT-GP  [QFN24-G2D8-UH24]  33.45 41.75 0 top
U3702  TPS70933DRVR-GP-U  [DFN6F2-G1711-UH32]  23.26 98.16 270 top
U3703  AP2141DFMG-7-GP  [DFN6G1820-G1511-UH24]  29.36 46.8 0 top
U3704  AP2141DFMG-7-GP  [DFN6G1820-G1511-UH24]  26.11 49.5 270 top
U3801  PS8740BQFN40GTR-A0-GP  [QFN40J4060-G275475H32]  33.7 59.15 180 top
U4001  G5016KD1U-GP  [DFN14J3020-G255D85H32]  134.29 102.07 270 bottom
U4002  APE8939GN3-GP  [DFN8F3-G245165H34]  91.97 91.36 90 top
U4004  TPS22961DNYT-GP  [DFN8F3-G2517H32]  99.39 93.79 90 top
U4005  74LVC1G07GW-GP  [SC70-5H44]  101.55 11.83 90 bottom
U4006  TPS22965DSGR-GP-U  [DFN8G2-G1710-U1H32]  108.51 16.15 270 bottom
U4101  SY6288C10CAC-GP  [MSOP8-1H44]  108.74 10.99 90 bottom
U4301  S-1004NA23I-M5T1U-GP  [SOT-23-5H52]  28.4 92.73 0 bottom
U4302  S-1004NA23I-M5T1U-GP  [SOT-23-5H52]  22.66 81.58 90 bottom
U5501  RT9724GB-GP  [SOT-23-5H51]  81.79 98.19 90 top
U5701  PS8407ATQFN40GTR2-A1-GP  [QFN40J5-G3D65H32]  22.65 65.84 270 top
U6001  AZ1045-04F-R7G-GP  [DFN10G2510H26]  174.42 13.94 270 top
U6002  TPS22965DSGR-GP-U  [DFN8G2-G1710-U1H32]  174.67 17.42 90 top
U6901  STM32L151CBU6TR-GP  [QFN48G7-G5D7H26]  39.17 28.92 90 top
U7001  LNG2DMTR-GP  [LGA12G2H40]  177.16 42.76 270 top
USB1  SKT-USB36-9-GP-U  [SKT-USB36-124103-1]  2.19 94.21 90 bottom
USB2  SKT-USB13-221-GP  [SKT-USB13-160162-2]  6.5 53.03 90 bottom
USB3  SKT-USB13-221-GP  [SKT-USB13-160162-2]  6.5 32.43 90 bottom
X1801  XTAL-24MHZ-81-GP  [OSC-3225-4P-4H36]  134.14 50.84 270 bottom
X1802  XTAL-32D768KHZ-67-GP  [SMD49-6914-0403H56]  105.28 23.16 0 bottom
X2401  XTAL-32D768KHZ-83-GP  [SMD49-3215-0713H36]  201.32 26 180 top
X6901  XTAL-12MHZ-67-GP  [OSC-3225-4P-4H36]  31.32 31.44 270 top

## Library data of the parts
AFTP2601-AFTP2604 AFTP2901-AFTP2904 AFTP6301 AFTP6303 AFTP6304 AFTP6501-AFTP6524 AFTP6529-AFTP6539 = AFTE14P-75: tolerance: ZZ.AFT14.101
AFTP4301-AFTP4315 AFTP4601 = AFTE14P-75
BATT1 = 50299-01001-002: tolerance: 20.F2460.010
C701-C704 C715 C1120 C1123 C1202-C1206 C1208-C1210 C1303-C1310 C1324 C1325 C1704 C2601 C2702 C2706 C2708 C2712 C2713 C2718 C2902 C2907 C2908 C3513 C3514 C3713 C4006 C4009 C4012 C7004 PC1107-PC1109 PC5115 PC5403 PC5414 = C603H38: tolerance: 78.10610.5BL
C716 C717 C719 C1101 C1105 C1107 C1109-C1111 C1114 C1116 C1117 C1119 C1121 C1124-C1127 C1207 C1214-C1221 C1225 C1226 C1313 C1315-C1322 C1326 C1327 C1805 C1806 C2101-C2109 C2116 C2117 C2120 C2121 C2418 C2426 C2714 C3401 C3508 C3703 C3704 C4015 C4023 C4031-C4034 C4101 C4102 C5508 C6901 EC1005 PC4428 PC4431 PC4438 PC4631 PC4708 PC4808 PC4847 PC5110 PC5111 PC5202 PC5401 PC5408-PC5410 = C402H22: tolerance: 78.10523.5FL
C718 C720 C721 C1229 C1301 C1601 C1602 C1702 C1703 C2110-C2112 C2118 C2406-C2408 C2410-C2414 C2416 C2420-C2423 C2428 C2429 C2502 C2602 C2605 C2608-C2610 C2612 C2701 C2707 C2709 C2710 C2717 C2719-C2722 C3402 C3403 C3502 C3503 C3507 C3601-C3604 C3701 C3702 C3705 C3706 C3709 C3714 C3801-C3819 C3861-C3864 C4007 C4008 C4011 C4014 C4017 C4028 C4029 C5501 C5504 C5506 C5507 C5509-C5511 C5519 C5531-C5533 C5701-C5716 C6002 C6007 C6008 C6010 C6307 C6501-C6504 C6902 C6906 C6907 C7002 C7003 EC1707 EC1712 EC1806-EC1808 EC1902 EC4001 PC4513 PC4518 PC4528 PC5102 PC5116 PC5118 PC5427 = C402H22: tolerance: 78.10421.2FL
C1102-C1104 C1106 C1108 EC1001-EC1004 EC1006 EC1007 EC4306 EC4307 EC4309 EC4310 PC4304 PC4305 PC4410 PC4411 PC4508 PC4530-PC4532 PC4709 PC4810 PC4814 PC5119 PC5120 PC5138 PC5406 PC5407 = C402H22
C1112 C1113 C1115 C1118 C1122 C2113-C2115 C2119 C2122 C3404 C3405 PC1001-PC1032 PC1034 PC1036-PC1078 PC1102 PC1103 PC1105 PC1106 PC1115 PC5201 PC5203 PC5205 PC5206 = C603H40: tolerance: 78.22610.5BL
C1211 C1212 C1223 C1224 C1227 C1230-C1232 C1311 C1312 C1330 C1331 = C402H22: tolerance: 078.47510.05FD
C1213 C1314 = C402H22: tolerance: 78.10523.L2L
C1222 C1323 = C402H22: tolerance: 78.22321.2FL
C1228 C1328 = C402H22: tolerance: 78.10421.L0L
C1329 R1216 = C603H36: tolerance: 78.22523.L1L
C1605-C1612 C6301-C6303 C6309 = C402H22: tolerance: 78.22423.5FL
C1701 EC6401 EC6402 PC4609 PC5212 = C402H22: tolerance: 78.22124.2FL
C1710 C2503 = C402H22: tolerance: 78.47423.5FL
C1711 C2409 C6001 C6003 C6005 C6006 C6903-C6905 PC4303 PC4606 PC4607 PC4616 PC4626 PC4629 PC5107 PC5213 = C402H22: tolerance: 78.10324.2FL
C1801 C1802 C6908 C6909 PC4604 PC4619 = C402H22: tolerance: 78.15034.1FL
C1803 C1804 = C402H22: tolerance: 78.3R074.1FL
C2402 C2403 D502 EC401 EC1701-EC1705 EC1708 EC1709 EC1711 ED1217 ED1302 ED2902-ED2905 = SOD882-10D6-1H20: tolerance: 83.05725.0A0
C2405 C2613 EC2901-EC2912 PC4310 PC4311 PC4621 = C402H22: tolerance: 78.10134.1FL
C2424 C2425 EC1801 EC1802 EC1901 EC2503 PC4617 = C402H22: tolerance: 78.10034.1FL
C2427 C2435 C2441 C2603 C2607 EC8906 EC8933-EC8935 PC4403 PC4404 PC4421 PC4422 PC4424 PC4430 PC4434 PC4612 PC4618 PC5031 = C402H22: tolerance: 78.22224.2FL
C2501 C4004 C4005 C4010 C4013 = C805H54: tolerance: 78.10623.51L
C2604 C2711 C2715 C2716 C2724 C5502 C5503 C5505 C5515 C5517 PC4507 = C603H36: tolerance: 78.47520.5BL
C2606 = C603H36: tolerance: 78.47134.1BL
C2703 C2704 = C603H36: tolerance: 78.10523.5BL
C2705 C3710 C3820 PC4524 PC5001 PC5113 = C603H36: tolerance: 78.22523.5BL
C2723 C6304 C6305 EC2701 EC2708 EC2709 EC5505 EC6501-EC6504 EC6601-EC6603 = C402H22: tolerance: 78.33034.1FL
C3512 PC4509-PC4511 PC4514-PC4517 PC4525 PC4527 PC4529 PC5101 PC5103-PC5105 PC5114 PC5412 = C805H58: tolerance: 78.22610.51L
C3707 EC8905 EC8927-EC8929 PC4301 = C603H32: tolerance: 78.10524.5BL
C3708 C3821 EC2101 EC2703 EC2705 EC4302 EC5502 EC8901 EC8903 EC8907-EC8917 EC8919-EC8925 EC8936-EC8938 PC1110-PC1113 PC4312 PC4402 PC4409 PC4419 PC4420 PC4501 PC4506 PC4521 PC4522 PC4610 PC4628 PC4630 PC4710 PC4811 PC4812 PC5002 PC5117 PC5204 PC5208 = C402H22: tolerance: 78.10422.5FL
C3711 C3712 = C402H22: tolerance: 78.39124.2FL
C4001 C4002 PC4613-PC4615 = C402H22: tolerance: 78.47124.2FL
C5512 C5516 C5542 PC4302 PC4416 PC5214 = C603H36: tolerance: 78.10424.2BL
C5513 C5534 EC1706 EC2002 EC2704 EC2706 EC2707 EC8902 EC8904 EC8918 PC4436 PC4437 PC4526 PC4533 PC4603 PC4605 PC4608 PC4611 PC4620 PC4623 PC4625 PC4627 PC4632 PC4633 PC5215 = C402H22: tolerance: 78.10224.2FL
C5514 C5518 = C603H40: tolerance: 078.22529.05B1
C6004 EC1102 EC1103 EC1202 EC1302 EC1303 EC1710 EC1713 EC4425 EC4534 EC8926 PC4413 PC4707 PC4807 PC4846 = C402H22: tolerance: 78.22523.5FL
C6009 = C402H22: tolerance: 78.10520.5FL
C6306 C6308 = C402H22: tolerance: 78.47322.2FL
C7001 = C402H22: tolerance: 78.47321.2FL
CPU1 = BGA1356M4224-U2H52: tolerance: 071.SKYLA.000U
D401 D1701 D2402 D2403 = SOD323AKH38: tolerance: 83.R2004.G8F
D2501 = SOT-23-9H44: tolerance: 75.00040.07D
D2601 = SOD323AKH44: tolerance: 083.55130.008F
D2701 D5501 D5502 = SOT23-2D4-312H48: tolerance: 75.00054.E7D
D3701 D3702 D4003 D4004 = SOD923-10D6AKH16: tolerance: 083.00521.0D8F
D3703 D3704 = SOD323AKH38: tolerance: 83.R5003.H8H
D4001 = SOT23-2D4-312H44: tolerance: 83.00016.P11
D4002 = SOT23-2D4-312H44: tolerance: 83.00016.K11
D4304-D4306 PD4302 = SOT23-2D4-312H44: tolerance: 75.00099.O7D
D5701 = SOT-23-10H44: tolerance: 75.00056.07D
D7001 = SOT23-2D4-312H48: tolerance: 75.00054.R7D
DB1 = PAD-10P-177042: tolerance: ZZ.00PAD.Y41
DB3 = 50696-00601-001: tolerance: 20.K0691.006
DCIN1 = 50224-0080N-W02: tolerance: 20.F1295.008
DM1 = ADDR0107-P005A: tolerance: 062.10011.00U1
DM2 = ADDR0106-P005A: tolerance: 062.10011.00T1
EC1803 EC2501 EC2502 = C402H22: tolerance: 78.4R7B4.1FL
EC4301 PC4306 = C603H40: tolerance: 78.10612.5BL
EC4308 = C603H36
EC5501 = C402H22: tolerance: 78.6R864.1FL
EC5503 EC5504 = C402H22: tolerance: 78.22034.1FL
ED2901 ED2906 = SOD-523-4H28: tolerance: 75.02025.077
ED3801 EU3804 = SOT883-1D0-321H20: tolerance: 83.05315.0A0
ED6301 = SLP2510P8-1H22: tolerance: 075.00550.0071
ED6401 ED6402 = SOD-523-2H26: tolerance: 83.0005V.0AF
EL2901-EL2904 = L402H22: tolerance: 68.00084.G41
EL4301-EL4304 R4101 = R805H24: tolerance: 63.R0031.16L
EU3601 EU3603 EU3801-EU3803 = LGA9G2310H13: tolerance: 83.3V3U4.0A0
EU3602 EU3604 = SOT-6H58: tolerance: 75.09904.07C
F5501 F5503 = POLYSW-4633-UH43: tolerance: 69.50007.A31
F5502 F6501 = POLYSW-2114H50: tolerance: 69.50007.921
F5504 F5701 = POLYSW-2114H30: tolerance: 69.48001.081
FAN1 = 50224-0040N-001: tolerance: 20.F1639.004
G1801 = CON2O-U: tolerance: ZZ.CON2O.XXX
GMR1 = OPLGA4-0913H22: tolerance: 074.00013.00BJ
GPU1 = XBGCB5009: tolerance: 020.F0581.0048
GPU2 = XBGCB5008: tolerance: 020.F0588.0028
H2 H4 H7-H10 = HOLE335R178: tolerance: ZZ.00PAD.7F1
H3 H5 H6 = HOLE335R229: tolerance: ZZ.00PAD.7G1
HDA27 = QFN48J6-G465H40: tolerance: 071.03253.0003
HDD1 = GS12201-1011-9H: tolerance: 20.F1546.020
HDMI1 = SKT-HDMI23-188137-2: tolerance: 22.10296.961
HPMIC1 = AJ3R2D-Y050-412: tolerance: 022.10002.00D1
HS1 = STF217R115H101: tolerance: 34.4Y802.011
HS2 HS3 = STFSR158R113H62: tolerance: 434.07R01.0001
IOBD1 = 20455-050E-76: tolerance: 020.F0574.0050
KBBD1 = 51540-04401-W01: tolerance: 20.K0809.044
KBC24 = TQFP128J16H48: tolerance: 071.01404.0B0E
LCD1 = 20455-040E-12: tolerance: 20.F1407.040
PC1101 PC1104 PC1114 = C603H40
PC4307 = C402H22: tolerance: 78.15423.5FL
PC4405-PC4408 PC4415 PC4418 PC4433 PC4435 PC4701-PC4705 PC4802-PC4806 PC4820 PC4827-PC4830 PC5027 PC5029 PC5108 PC5209-PC5211 PC5216 = C805H56: tolerance: 78.10622.51L
PC4412 = C805H58: tolerance: 78.10594.41L
PC4414 PC4426 PC4706 PC4809 PC4845 PC5008 = C603H40: tolerance: 78.22422.2BL
PC4417 PC4502-PC4505 PC4519 PC4523 = C603H40: tolerance: 078.10612.05BN
PC4423 = C402H22: tolerance: 78.22234.2FL
PC4427 = C402H24: tolerance: 78.56124.2FL
PC4432 PC4634 = C402H22: tolerance: 78.22322.2FL
PC4512 PC5404 = C805H58
PC4520 = C805H54: tolerance: 78.47522.51L
PC4601 = C402H22: tolerance: 78.15224.2FL
PC4602 = C402H22: tolerance: 78.15322.2FL
PC4622 PC4624 = C402H22: tolerance: 78.33322.2FL
PC5106 = C805H56
PC5112 = C402H22: tolerance: 78.33124.2FL
PC5402 PC5413 = C805H54: tolerance: 78.10620.51L
PC5405 PC5411 = C402H22: tolerance: 78.68034.1FL
PD4301 = SOD323AKH38: tolerance: 83.2R004.08F
PD4303 = SOT23-2D4-312H60: tolerance: 83.03024.0A1
PD4304 = SOD123FLAKH40
PD4305 PD4306 PD4409 PD4411 = SOD323AKH38: tolerance: 83.R2004.B8F
PD4401 PD4402 PD4405-PD4407 = SOD323-2513AKH36: tolerance: 83.R2004.J8F
PD4404 = SOD323AKH44: tolerance: 83.00355.G1F
PG4401 PG4408 PG4414 PG4415 PG4419 PG4501-PG4524 PG4527-PG4532 PG4601 PG4707 PG4708 PG4808 PG4809 PG4815 PG4816 PG5101-PG5104 PG5106-PG5114 PG5120 PG5121 PG5408 PG5409 = GAP-CLOSE-PWR-3
PG4402 PG4403 PG4409 PG4410 PG4412 PG4413 PG5223 = GAP-CLOSE-PWR: tolerance: ZZ.CLOSE.011
PG4404-PG4407 PG5201 PG5204 PG5206-PG5216 PG5404-PG5407 = GAP-CLOSE-PWR
PG5021 PG5022 = GAP-CLOSE-PWR-3: tolerance: ZZ.CLOSE.001
PG5023-PG5031 = GAP-CLOSE-PWR: tolerance: ZZ.CON2D.XXX
PL4401 = L7066-1830-UH119: tolerance: 68.4R71A.20H
PL4501 = L4947-1015H119: tolerance: 68.1R550.20C
PL4502 PL5201 = L686647-127318H119: tolerance: 68.1R01B.10K
PL4701 PL4801 PL4802 = L7366-1930H158: tolerance: 68.R1510.20A
PL5001 = L7066-1830-UH119: tolerance: 68.R4710.20F
PL5101 = L4947-1115H119: tolerance: 68.1R010.20R
PQ4301 Q501 = SOT23DGS2D4H48: tolerance: 84.05067.031
PQ4302 Q2603 = SOT23CBE2D6H46: tolerance: 84.03904.P11
PQ4304 = SOT323CBE2D2H40: tolerance: 84.05212.B11
PQ4305 = SC70-2D2-312H44: tolerance: 84.00024.01K
PQ4306-PQ4311 PQ4405 PQ4415 Q1701 Q1702 Q1801 Q2416 Q2601 Q2604 Q2605 Q6504 Q7001 = SOT-363H44: tolerance: 84.2N702.A3F
PQ4408 = SOT23CBE2D4H44: tolerance: 84.T3906.A11
PR4302 = R402H16: tolerance: 64.15025.6DL
PR4303 R802 R1503 R1606-R1608 R1701 R1707 R1714 R1717 R1726 R1814 R1816 R1820 R1821 R2005 R2008-R2010 R2029 R2030 R2039-R2047 R2415 R2429 R2430 R2473 R2607 R2726 R2919 R2920 R3812-R3814 R4009 R4026-R4028 R4046 R5721 R6120 R6303 R6304 R6511 R6908-R6919 R7005 R7006 = R402H16: tolerance: 63.10334.1DL
PR4304 PR4328 R1836 R2717 R2912 R2913 R3707 R5706 R5707 = R402H16: tolerance: 63.22234.1DL
PR4305 = R402H16: tolerance: 63.33034.1DL
PR4306 PR4436 PR4463 PR4503 PR4508 PR4512 PR4530 PR4614 PR4622 PR4624 PR4669 PR5106 PR5401 PR5402 = R402H16
PR4307 = R603H22: tolerance: 63.24434.15L
PR4308 PR4321 R1719 = R402H16: tolerance: 64.47025.6DL
PR4309 PR4318 PR4335 PR4431 PR4505 PR4510 PR5208 R404 R405 R603 R803 R1715 R1722 R1727 R1737 R2417 R2434 R2436 R2449-R2451 R2454 R2480 R2489 R2495 R2496 R2711 R2722 R2728 R3501 R3703 R3801 R3802 R4031 R4032 R6508 R6509 R6902 R7001 R7011 R7018 = R402H16: tolerance: 63.10434.1DL
PR4310 R401 R417 R419 R604 R605 R1702 R1822-R1825 R1909 R2006 R2007 R2019 R2432 R2463 R4005 R6513 = R402H16: tolerance: 63.10234.1DL
PR4311 PR4319 PR4323 PR4324 PR4329 PR4332 PR4413 PR4423 PR4424 PR5203 R1716 R2441 R2444 = R402H16: tolerance: 64.10035.6DL
PR4312 = R402H16: tolerance: 64.47035.6DL
PR4313 = R402H16: tolerance: 64.71525.6DL
PR4314 = R1206H28: tolerance: 63.33232.11L
PR4315 = R402H16: tolerance: 64.18725.6DL
PR4316 R1731 R2727 R4043 R6907 = R402H16: tolerance: 63.20334.1DL
PR4317 PR4447 PR4501 PR4502 PR5101 R703 R1102-R1104 R1711 R2106-R2111 R2446 R2703 R2906 R2907 R2909 R2911 R2923 R5510 R5511 R5701 R5715 R6003 R6006 R6302 R6307 R6605 R6606 = 0R0603-PAD: tolerance: ZZ.R0603.ZZZ
PR4320 PR4330 PR4334 PR4337 = R402H16: tolerance: 64.24035.6DL
PR4322 PR4333 PR4420 PR4421 PR4438 PR4439 PR4450 PR4663 PR5103 PR5104 PR5204 PR5410 R1306 R2448 R2510 R3704 R3717 R3722 R3723 = R402H16: tolerance: 64.10025.6DL
PR4327 PR4640 = R402H16: tolerance: 64.12425.6DL
PR4331 = R402H16: tolerance: 64.12435.6DL
PR4336 = R402H16: tolerance: 63.68434.1DL
PR4338 = R2512H28: tolerance: 63.10135.17L
PR4339 R2442 = R402H16: tolerance: 64.64925.6DL
PR4401 PR4410 PR4449 PR4506 PR4507 PR4509 PR4511 PR4601 PR4619 PR4626 PR4642 = R402H16: tolerance: 64.10015.6DL
PR4402 PR4415 = R3720H40: tolerance: 64.R0105.7FL
PR4403 = R805H24: tolerance: 64.10005.16L
PR4407 = R805H24: tolerance: 63.2R231.16L
PR4408 = R402H16: tolerance: 64.30035.6DL
PR4409 = R402H16: tolerance: 64.37425.6DL
PR4411 PR4414 R1206 R1305 = R402H16: tolerance: 64.2R005.6DL
PR4412 = R603H22: tolerance: 64.4R705.55L
PR4416 PR4623 PR4668 R503 R719-R722 R724-R726 R729 R731 R734 R735 R1501 R1604 = R402H14: tolerance: 64.10005.6DL
PR4422 PR4445 PR4471 = R402H16: tolerance: 64.10035.L1L
PR4430 PR4444 PR4448 PR4455 PR4458 PR4462 PR4504 PR4515 PR4516 PR4604 PR4607 PR4616-PR4618 PR4630 PR4645 PR4648 PR4650 PR4655 PR4666 PR4670 PR4671 PR4704 PR4808 PR5102 PR5105 PR5107 PR5114 PR5118 PR5125 PR5209 PR5405 PR5408 PR5417 R504 R602 R709 R732 R1205 R1210 R1212 R1303 R1311 R1706 R1713 R1732 R1801 R1810 R1812 R1813 R1819 R1908 R1911 R2022-R2028 R2101 R2402 R2403 R2407 R2419 R2435 R2445 R2462 R2470 R2472 R2475 R2515 R2602 R2611-R2614 R2708 R2713 R2714 R2716 R2718-R2720 R2723-R2725 R2905 R2921 R2922 R3401 R3402 R3405 R3406 R3605 R3606 R3609-R3614 R3701 R3702 R3705 R3706 R3709 R3710 R3718 R3832-R3839 R3843 R3846 R3849 R3850 R4002 R4010 R4011 R4017 R4023 R4024 R4029 R4030 R4036 R4038 R4042 R4044 R4301 R5501 R5503 R5540 R5722 R5723 R6001 R6002 R6301 R6305 R6403 R6404 R6510 R6512 R7003 R7004 R7007-R7010 R7012 R7013 = 0R0402-PAD: tolerance: ZZ.R0402.ZZZ
PR4433 = R402H16: tolerance: 64.15035.6DL
PR4437 = R402H16: tolerance: 64.49925.6DL
PR4442 = R402H15: tolerance: 63.47434.L0L
PR4443 = R402H16: tolerance: 64.30035.L0L
PR4451 = R402H16: tolerance: 64.68035.6DL
PR4513 PR4514 R1802 = R402H16: tolerance: 63.10534.1DL
PR4551 = R402H16: tolerance: 64.34835.6DL
PR4602 R6904 = R402H16: tolerance: 64.15015.6DL
PR4605 = R402H16: tolerance: 64.82505.6DL
PR4606 PR4633 PR4653 PR4656 = NTC-402H24-U: tolerance: 69.60028.011
PR4608 = R402H16: tolerance: 64.26115.6DL
PR4609 = R402H16: tolerance: 64.14325.6DL
PR4611 = R402H16: tolerance: 64.27425.6DL
PR4612 PR4627 = R603H22: tolerance: 64.80615.55L
PR4613 = R402H16: tolerance: 64.93125.6DL
PR4615 R2424 R3403 R4006 R6504 = R402H16: tolerance: 64.20025.6DL
PR4621 = R402H16: tolerance: 64.45R35.6DL
PR4625 = R402H16: tolerance: 64.37R45.6DL
PR4628 = R402H16: tolerance: 64.11035.6DL
PR4629 = R402H16: tolerance: 64.14025.6DL
PR4631 = R402H16: tolerance: 64.47515.6DL
PR4632 = R402H16: tolerance: 64.26125.6DL
PR4634 = NTC-402H24-U: tolerance: 69.60028.031
PR4635 = R402H16: tolerance: 64.59025.6DL
PR4636 PR4649 = R402H16: tolerance: 64.24915.6DL
PR4637 = R603H22: tolerance: 64.48725.55L
PR4638 = R402H16: tolerance: 64.16535.6DL
PR4639 = R402H16: tolerance: 64.75025.6DL
PR4641 = R603H22: tolerance: 64.73225.55L
PR4643 PR4646 PR4667 R1811 R2405 R2503 R2609 R2908 R2910 = R402H14: tolerance: 64.10R05.6DL
PR4644 = R402H16: tolerance: 64.42205.6DL
PR4647 = R402H16: tolerance: 64.38315.6DL
PR4651 PR4654 = R402H16: tolerance: 64.69815.6DL
PR4652 PR4661 = R402H16: tolerance: 64.12725.6DL
PR4657 PR4702 PR4803 PR4806 = R402H16: tolerance: 64.2R205.6DL
PR4658 = R402H16: tolerance: 64.90925.6DL
PR4659 PR4664 = R402H16: tolerance: 64.24025.6DL
PR4660 = R402H16: tolerance: 64.19125.6DL
PR4665 R412-R415 R601 = R402H16: tolerance: 64.49R95.6DL
PR4672 = R402H16: tolerance: 064.48725.06DD
PR4701 PR4802 PR4805 = R603H22: tolerance: 63.3R934.15L
PR4703 PR4804 PR4807 = R805H24
PR4809 PR5126 PR5207 PR5210 PR5406 PR5407 R410 R702 R704 R804 R1704 R1708 R1718 R1720 R1728 R1729 R1733 R2003 R2004 R2020 R2021 R2102 R2418 R2447 R2459 R2471 R2474 R2494 R2497 R2601 R2615 R2705 R2710 R2732 R3719-R3721 R3842 R3844 R3845 R3847 R3848 R4018 R4019 R4033 R4102 R4302 R4303 R5502 R6005 R6007 R6505 R6506 R6801 R6802 R6905 R6906 R6920-R6926 R6928 R6929 R7002 = R402H16: tolerance: 63.R0034.1DL
PR5013 = R603H22: tolerance: 64.2R205.55L
PR5014 = R805H24: tolerance: 64.2R205.16L
PR5201 = R402H16: tolerance: 64.88725.6DL
PR5202 = R402H16: tolerance: 64.25515.6DL
PR5403 = R402H16: tolerance: 64.16525.6DL
PR5404 = R402H16: tolerance: 64.13325.6DL
PR5409 = R402H16: tolerance: 63.47334.1DL
PR5419 = R402H16: tolerance: 64.29425.6DL
PR5420 = R402H16: tolerance: 64.13725.6DL
PT4701 PT4801 PT4803 = CT7343H83: tolerance: 79.33719.L01
PT4802 = CT7343H83
PT4805 PT4806 = CT7343H83: tolerance: 79.33612.20L
PU4301-PU4304 PU4403 = PPAK-8P-2H45: tolerance: 84.07121.037
PU4305 PU4306 = PPAK-8P-2H45: tolerance: 84.07625.037
PU4401 = QFN32J4-G2D7H42: tolerance: 074.95521.0A73
PU4404 PU4405 PU5002 PU5003 = PPAK-8P-2H45: tolerance: 84.00412.037
PU4501 = QFN20Z3-G1D1H36: tolerance: 074.08286.0043
PU4502 = QFN20Z3-G1D1H36: tolerance: 074.08288.0B43
PU4601 = LFQFN48J6-G4D6H40: tolerance: 074.81208.0D73
PU4701 PU4801 PU4802 = QFN36J4060-G2554H48: tolerance: 074.81382.0CE3
PU5001 = LFDFN8G2-G1309H40: tolerance: 074.81253.0AE3
PU5101 = QFN20Z3-G1H36: tolerance: 074.08288.0043
PU5102 = MSOP10-G2D5H44: tolerance: 74.05338.079
PU5201 = QFN22G4-G2PH42: tolerance: 074.02262.0043
PU5401 PU5403 = SOIC8-G3530H63: tolerance: 74.05930.03D
PU5402 = SOT-23-5H52: tolerance: 74.01339.B3F
Q1802 Q2408 Q2414 Q2415 Q2505 Q2602 Q2701 Q4008 Q5704 Q6105 Q6503 = SOT23DGS2D4H44: tolerance: 84.2N702.J31
Q2702 Q4009 Q6502 = SOT23DGS2D4H48: tolerance: 84.02130.031
Q4001 = SOT723DGS1D2H22: tolerance: 84.03K15.C31
Q6401 Q6402 Q6505 = SOT23CBE2D6H62: tolerance: 084.02418.0011
Q6501 = SOT23DGS2D8H56: tolerance: 84.P8503.031
R402 R406-R409 R416 R421-R423 = R402H16: tolerance: 63.51034.1DL
R403 R6401 = R402H16: tolerance: 64.49905.6DL
R501 = R402H16: tolerance: 64.12105.6DL
R502 = R402H16: tolerance: 64.80R65.6DL
R505 = R402H16: tolerance: 64.47005.6DL
R506 = R402H16: tolerance: 64.22035.6DL
R705 R1724 R1735 R2702 R2704 R2706 R2731 = 0R0805-PAD: tolerance: ZZ.R0805.ZZZ
R723 = R402H16: tolerance: 64.54R95.6DL
R727 = R402H16: tolerance: 63.56034.1DL
R728 = R402H16: tolerance: 63.22134.1DL
R801 R1209 R1309 = R402H16: tolerance: 64.24R95.6DL
R1101 R4021 R4022 R4045 = 0R1206-PAD: tolerance: ZZ.R1206.ZZZ
R1204 R1208 R1211 R1302 R1310 = R402H15: tolerance: 64.10025.L0L
R1215 R1312 = R402H16: tolerance: 64.24005.6DL
R1307 = R402H15: tolerance: 63.R0034.L0L
R1502 R1901 = R402H16: tolerance: 64.20005.6DL
R1603 = R402H16: tolerance: 64.11305.6DL
R1730 = R402H16: tolerance: 63.33434.1DL
R1803 = R402H16: tolerance: 64.27015.6DL
R1804 R1805 = R402H16: tolerance: 63.22034.1DL
R1815 R2504 = R402H16: tolerance: 63.10634.1DL
R1818 = R402H16: tolerance: 64.82015.6DL
R1837 = R402H16: tolerance: 63.15434.1DL
R2048 R2049 R6507 = R402H16: tolerance: 63.51334.1DL
R2414 R2501 R3708 R3810 R3811 R3815-R3824 R5411-R5420 = R402H16: tolerance: 63.47234.1DL
R2421-R2423 R6402 = R402H16: tolerance: 63.33134.1DL
R2437 = R402H16: tolerance: 63.43034.1DL
R2443 = R402H16: tolerance: 64.33025.6DL
R2603 R2604 = R402H16: tolerance: 64.75015.6DL
R2608 = R402H16: tolerance: 64.27025.6DL
R2610 = NTC-603H38: tolerance: 69.60035.041
R2709 = R402H16: tolerance: 64.20035.6DL
R3404 = R402H16: tolerance: 64.22125.6DL
R3711 R3712 = R402H16: tolerance: 63.20434.L0L
R3713-R3715 = R402H16: tolerance: 64.90935.6DL
R3716 = R402H16: tolerance: 64.30135.6DL
R3803 = R402H16: tolerance: 64.49915.6DL
R3830 R3831 = R402H16: tolerance: 64.20045.6DL
R4103 R5507 R5513 R5516 R5520 R5716 R6501 R6502 R6514 R6901 = R603H22: tolerance: 63.00000.00L
R5506 = R402H14: tolerance: 63.10134.1DL
R5514 = R1206H26: tolerance: 63.R0037.L0L
R5702-R5705 = R402H16: tolerance: 63.18134.1DL
R5710 = R402H16: tolerance: 63.43234.1DL
R6503 = R603H22: tolerance: 63.10133.15L
RN801 RN803 RN1811 RN1814 RN1815 RN2008 RN2602-RN2604 RN2901 RN6503 RN6901 = ARES2H16: tolerance: 66.22236.04L
RN1201 RN1301 RN1802 RN2007 RN2701 = SMD-ARES4H18: tolerance: 66.10236.04L
RN1601 RN1704 RN1812 RN1813 RN2403 RN2404 = ARES8-CN24-MUH20: tolerance: 66.10336.08L
RN1602 RN1702 RN7001 = SMD-ARES4H20: tolerance: 66.R0036.04L
RN1703 RN1810 RN2009 RN2407 RN6501 = ARES2H18: tolerance: 66.10336.04L
RN1801 = SMD-ARES4H20: tolerance: 66.20336.04L
RN1803 = ARES8-CN24-UH18: tolerance: 66.10036.08A
RN1806 RN6801 = ARES8-CN24H22: tolerance: 66.R0036.A8L
RN1807 = ARES8-CN24-UH20: tolerance: 66.22236.A8L
RN1902 RN5503 RN6502 = SMD-ARES4H18: tolerance: 66.33036.04L
RN2402 = SMD-ARES4H18: tolerance: 66.47236.04L
RN2405 RN2409-RN2412 RN5502 = ARES8-CN24H20: tolerance: 66.10436.A8L
RN2406 RN2502 RN2503 = SMD-ARES4-2H18-U: tolerance: 66.10035.04L
RN4302 RN5501 = ARES8-CN24H20: tolerance: 66.10136.A8L
SKT251 = G6179HT0321-001: tolerance: 62.10089.011
SPI25 = SOIC8-1H86: tolerance: 72.25128.0B1
SPK1 = A1001WR-S06PN6BT1TS2R-U: tolerance: 20.F1804.006
SPR1-SPR3 = SPR5128H111: tolerance: 34.4YW18.001
SPR4 = SPR6238H60: tolerance: 34.43E25.001
SSD1 = AS0BC2Y-S30BM-7H: tolerance: 062.10003.0481
TC3501 = C1206H71: tolerance: 78.10710.52L
TCBD1 = FL10F032HA2R3000: tolerance: 20.K0801.032
THM261 = MSOP8-1H44: tolerance: 74.07718.0B9
TP401-TP408 TP601-TP615 TP617-TP638 TP701 TP707 TP801 TP1602-TP1606 TP1703-TP1712 TP1801-TP1807 TP1902 TP1903 TP2006 TP2012-TP2014 TP2016-TP2018 TP2101 TP2102 TP2301-TP2313 TP2702 TP2901 TP2902 TP3701-TP3703 TP6901-TP6904 = TPAD14-OP: tolerance: ZZ.PAD14.001
TR3602 TR3603 TR5501 = L125100-4P-4H37: tolerance: 68.11900.201
TR3805 = L125100-4PH24: tolerance: 068.24900.2001
TR6601 TR6602 = L125100-4P-4H24: tolerance: 68.00396.001
U1701 U1703 U4005 = SC70-5H44: tolerance: 73.01G07.0HG
U3401 = QFN16-G1D8-UH32: tolerance: 74.02544.073
U3501 U3502 = SOT-23-5H56: tolerance: 074.06288.009B
U3701 = QFN24-G2D8-UH24: tolerance: 071.02122.0003
U3702 = DFN6F2-G1711-UH32: tolerance: 074.70933.0033
